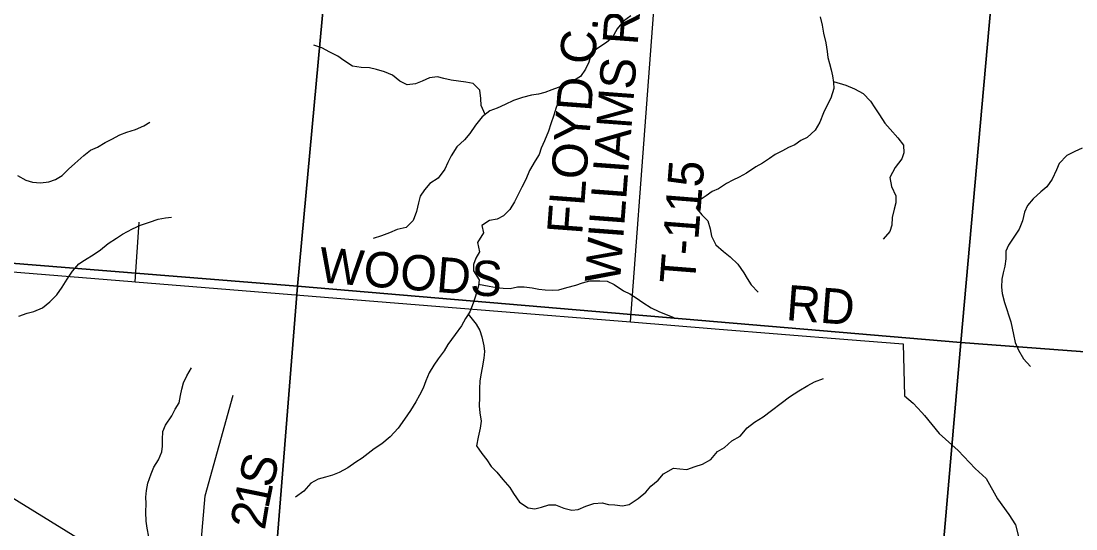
# Model space of a CAD drawing. Extents: x 1715311 to 2083412, y 146837 to 553079.
# Drawn here: x 1957824 to 1966796, y 323512 to 327826 of the extents above; entities that cross this region are included whole.
import ezdxf

# ---------------------------------------------------------------- set-up
doc = ezdxf.new("R2010")
doc.units = 0
for name, color, linetype in [('GM_X_Minor_River', 7, 'Continuous'), ('GM_X_Section', 7, 'Continuous'), ('GM_X_State_Route', 7, 'Continuous'), ('GM_X_Township_Road', 7, 'Continuous'), ('GM_X_Township_Road_Text', 7, 'Continuous')]:
    doc.layers.add(name, color=color, linetype=linetype)

msp = doc.modelspace()

# ---------------------------------------------------------------- linework, layer by layer
at = {"layer": 'GM_X_Minor_River'}
for points in [[(1963011.1, 327870.8), (1962949, 327825.1), (1962894.9, 327759.3), (1962852.6, 327683.4), (1962802.6, 327645.6), (1962728.5, 327595.9), (1962676.5, 327558.1), (1962652.2, 327478.2), (1962624, 327418.2), (1962581.8, 327356.4), (1962515.8, 327316.7), (1962461.8, 327286.9), (1962391.8, 327263.2), (1962337.8, 327243.4), (1962277.9, 327219.7), (1962223.9, 327205.9), (1962166, 327196.2), (1962090.1, 327178.5), (1962012.2, 327152.8), (1961942.2, 327119.1), (1961874.2, 327085.4), (1961810.2, 327063.7), (1961746.2, 327013.9), (1961690, 326942.1), (1961639.8, 326870.3), (1961595.6, 326816.5), (1961531.5, 326758.7), (1961481.3, 326680.9), (1961453.1, 326625), (1961426.9, 326569), (1961370.7, 326493.2), (1961300.7, 326445.5), (1961254.6, 326393.7), (1961218.4, 326339.8), (1961204.2, 326281.8), (1961185.9, 326207.9), (1961159.6, 326131.9), (1961099.5, 326074.1), (1961023.6, 326056.5), (1960957.6, 326028.8), (1960889.7, 326003), (1960819.7, 325979.3)], [(1964621.5, 327861.5), (1964637.1, 327791.4), (1964648.8, 327723.3), (1964668.4, 327643.1), (1964680.1, 327569), (1964685.8, 327517), (1964699.6, 327466.9), (1964715.3, 327412.8), (1964727.1, 327360.7), (1964734.8, 327304.6), (1964736.6, 327252.5), (1964712.3, 327170.6), (1964684.1, 327116.7), (1964649.9, 327046.8), (1964617.6, 326966.9), (1964579.4, 326899), (1964509.3, 326837.3), (1964457.3, 326811.5), (1964405.2, 326775.7), (1964351.3, 326751.9), (1964299.3, 326724.1), (1964239.3, 326694.4), (1964189.2, 326658.6), (1964129.2, 326618.8), (1964073.2, 326587), (1963993.1, 326535.4), (1963931.1, 326499.6), (1963879.1, 326473.8), (1963825.1, 326446.1), (1963755.1, 326400.4), (1963703.1, 326378.6), (1963651, 326342.8), (1963601, 326309), (1963564.8, 326239.1), (1963614.4, 326180.8), (1963664.1, 326128.6), (1963685.7, 326060.4), (1963695.5, 326000.3), (1963733, 325924.1), (1963798.7, 325869.8), (1963856.3, 325823.5), (1963921.9, 325761.1), (1963971.5, 325688.8), (1963999.2, 325638.7), (1964034.9, 325586.5), (1964092.5, 325522.2)], [(1961771.1, 327033.3), (1961736.6, 327110), (1961734.9, 327170.1), (1961725.2, 327240.2), (1961669.6, 327296.5), (1961607.7, 327306.8), (1961482.1, 327325.4), (1961418.3, 327339.7), (1961366.5, 327353.9), (1961296.6, 327344.2), (1961236.6, 327316.5), (1961178.6, 327292.7), (1961108.7, 327285), (1961045, 327317.3), (1960983.4, 327367.6), (1960915.6, 327396), (1960847.9, 327416.3), (1960786.1, 327428.6), (1960716.3, 327430.9), (1960642.5, 327443.2), (1960568.8, 327491.6), (1960517.1, 327527.9), (1960451.4, 327562.2), (1960381.7, 327600.5), (1960314, 327622.9)], [(1964733.5, 327314.1), (1964840.5, 327282.1), (1964914.2, 327251.7), (1964987.9, 327211.4), (1965049.4, 327147), (1965085.1, 327090.8), (1965124.8, 327030.6), (1965170.4, 326960.3), (1965216, 326908.1), (1965281.6, 326833.8), (1965329.2, 326771.5), (1965332.9, 326707.4), (1965314.7, 326655.5), (1965258.5, 326581.7), (1965214.3, 326497.8), (1965227.9, 326421.7), (1965265.5, 326341.5), (1965263.2, 326281.4), (1965249, 326227.5), (1965234.7, 326157.5), (1965230.5, 326091.4), (1965212.3, 326037.5), (1965158.1, 325973.7)], [(1962422.2, 327273.5), (1962411.5, 327199), (1962393.3, 327137.1), (1962373.1, 327085.1), (1962354.9, 327027.2), (1962330.6, 326953.2), (1962310.4, 326891.3), (1962276.1, 326809.4), (1962247.9, 326747.5), (1962229.7, 326693.5), (1962195.5, 326639.6), (1962149.3, 326555.8), (1962117, 326479.8), (1962082.8, 326416), (1962052.6, 326352), (1962020.4, 326292.1), (1961982.2, 326226.3), (1961928.1, 326172.5), (1961872.1, 326142.7), (1961808.2, 326133), (1961744.2, 326089.2), (1961757.9, 326027.1), (1961705.6, 325945.3), (1961723.2, 325865.2), (1961691.1, 325813.3), (1961672.9, 325757.3), (1961672.6, 325705.3), (1961720.2, 325627), (1961714, 325577), (1961687.7, 325489), (1961669.5, 325429.1), (1961641.2, 325357.2), (1961605, 325299.3), (1961570.8, 325237.4), (1961516.6, 325163.6), (1961454.4, 325079.8), (1961422.2, 325023.9), (1961372.1, 324958.1), (1961333.9, 324904.2), (1961293.7, 324838.3), (1961267.5, 324770.4), (1961243.3, 324706.5), (1961213.1, 324648.6), (1961180.9, 324590.7), (1961136.7, 324516.8), (1961086.5, 324443), (1961032.3, 324369.2), (1960962.1, 324293.4), (1960892, 324233.7), (1960827.9, 324192), (1960775.9, 324152.2), (1960725.8, 324112.4), (1960671.8, 324078.6), (1960601.7, 324030.9), (1960529.7, 323991.2), (1960473.8, 323969.4), (1960413.8, 323951.7), (1960351.9, 323935.9), (1960287.9, 323900.2), (1960229.7, 323832.4), (1960157.7, 323782.7)], [(1957792.8, 326515.4), (1957864.4, 326475.1), (1957920.2, 326456.8), (1957990.1, 326452.5), (1958059.9, 326460.2), (1958115.9, 326479.9), (1958173.9, 326515.7), (1958226, 326569.5), (1958280.1, 326617.3), (1958358.2, 326685), (1958414.3, 326728.8), (1958472.3, 326756.5), (1958538.3, 326796.3), (1958596.3, 326824), (1958664.3, 326859.8), (1958722.3, 326883.5), (1958796.2, 326905.2), (1958868.2, 326936.9), (1958920.2, 326966.7)], [(1966849.7, 326746.6), (1966787.7, 326718.8), (1966717.7, 326685.1), (1966653.6, 326615.4), (1966631.4, 326561.4), (1966595.1, 326483.5), (1966549, 326417.7), (1966498.9, 326375.9), (1966432.8, 326316.1), (1966384.6, 326258.3), (1966358.5, 326202.4), (1966342.2, 326130.4), (1966313.9, 326058.5), (1966263.7, 325982.7), (1966221.5, 325922.8), (1966199.4, 325870.9), (1966199.1, 325806.8), (1966192.8, 325744.8), (1966176.6, 325686.8), (1966166.4, 325634.8), (1966162.1, 325566.8), (1966169.9, 325512.7), (1966187.5, 325434.6), (1966205.2, 325384.5), (1966224.9, 325322.3), (1966242.7, 325272.2), (1966254.4, 325216.1), (1966264.2, 325164), (1966279.8, 325095.9), (1966307.5, 325029.7), (1966351.1, 324955.5), (1966410.6, 324891.2)], [(1957803.5, 325318.5), (1957875.5, 325344.2), (1957933.4, 325357.9), (1958005.4, 325391.6), (1958069.5, 325441.4), (1958127.6, 325501.1), (1958173.8, 325567), (1958216, 325632.8), (1958260.2, 325702.7), (1958314.3, 325764.5), (1958364.4, 325794.3), (1958444.4, 325846), (1958498.5, 325883.8), (1958564.5, 325935.5), (1958634.6, 325983.2), (1958686.6, 326015), (1958770.6, 326060.7), (1958840.6, 326092.4), (1958916.5, 326118), (1958988.5, 326143.8), (1959052.4, 326155.5), (1959104.3, 326161.2)], [(1961715.6, 325590), (1961805.8, 325574.6), (1961867.6, 325562.3), (1961925.4, 325556), (1961983.3, 325555.8), (1962047.2, 325567.5), (1962103.1, 325569.2), (1962170.9, 325558.9), (1962226.7, 325548.6), (1962280.6, 325544.4), (1962340.5, 325540.1), (1962398.3, 325543.9), (1962466.3, 325563.6), (1962542.2, 325583.2), (1962600.1, 325603), (1962662.1, 325620.7), (1962745.9, 325620.3), (1962809.7, 325616), (1962867.5, 325589.8), (1962949.1, 325533.4), (1963002.9, 325509.1), (1963054.6, 325474.8), (1963112.3, 325434.5), (1963181.9, 325390.2), (1963249.7, 325357.9), (1963311.4, 325333.6), (1963377.2, 325307.2)], [(1961628, 325336), (1961694.6, 325250.8), (1961726.3, 325198.6), (1961742.1, 325144.5), (1961759.7, 325068.4), (1961765.5, 325018.3), (1961761.2, 324962.3), (1961746.9, 324880.3), (1961734.7, 324820.3), (1961724.5, 324766.3), (1961722.2, 324704.3), (1961721.9, 324628.2), (1961719.6, 324556.2), (1961727.3, 324498.1), (1961737, 324426), (1961728.7, 324368), (1961710.4, 324292), (1961698.1, 324218), (1961741.8, 324151.8), (1961785.4, 324097.6), (1961823.1, 324043.3), (1961870.8, 323993.1), (1961922.4, 323932.8), (1961980, 323864.5), (1962011.7, 323812.3), (1962063.2, 323738), (1962136.9, 323691.7), (1962194.7, 323681.4), (1962250.7, 323697.1), (1962312.6, 323716.9), (1962368.5, 323716.6), (1962440.2, 323688.3), (1962508, 323670), (1962561.9, 323675.7), (1962627.9, 323705.4), (1962695.8, 323729.1), (1962765.7, 323732.8), (1962819.5, 323720.6), (1962875.4, 323716.3), (1962939.2, 323708), (1962997.1, 323719.8), (1963073.2, 323769.5), (1963137.2, 323823.2), (1963181.4, 323875.1), (1963241.5, 323924.8), (1963289.6, 323980.6), (1963373.6, 324028.3), (1963427.5, 324022), (1963485.3, 324015.8), (1963557.3, 324043.5), (1963619.2, 324061.2), (1963691.2, 324102.9), (1963747.4, 324170.7), (1963807.4, 324204.5), (1963869.5, 324260.2), (1963939.5, 324299.9), (1963999.7, 324371.7), (1964061.8, 324419.5), (1964135.8, 324465.2), (1964205.9, 324516.9), (1964288, 324580.6), (1964360.1, 324634.3), (1964440.1, 324686), (1964516.1, 324731.6), (1964572.1, 324761.4), (1964650.1, 324791.1)], [(1958909, 323444.1), (1958897.3, 323518.2), (1958887.6, 323576.3), (1958883.9, 323654.4), (1958888.2, 323726.4), (1958884.5, 323780.5), (1958890.7, 323838.5), (1958901, 323900.5), (1958929.2, 323978.4), (1958953.4, 324036.3), (1958991.6, 324098.2), (1959019.8, 324166.1), (1959026, 324216.1), (1959026.3, 324272.2), (1959030.6, 324338.2), (1959050.8, 324394.2), (1959107, 324472), (1959135.2, 324527.9), (1959167.3, 324581.8), (1959179.6, 324645.8), (1959191.8, 324699.8), (1959204, 324751.7), (1959234.2, 324813.6), (1959274.4, 324879.5)]]:
    msp.add_lwpolyline(points, dxfattribs=at)
at = {"layer": 'GM_X_Section'}
for points in [[(1960667.9, 330918.2), (1960176.2, 325575.7), (1954563.6, 326023.5), (1954897.2, 331252.1)], [(1960667.9, 330918.2), (1966300.5, 330486.3), (1965818.8, 325095.8), (1960176.2, 325575.7)], [(1966300.5, 330486.3), (1971868, 329980.4), (1971431.7, 324673.2), (1965818.8, 325095.8)], [(1954563.6, 326023.5), (1960176.2, 325575.7), (1959744.5, 320189.1), (1954105.8, 320629)], [(1960176.2, 325575.7), (1965818.8, 325095.8), (1965361.2, 319827.2), (1959744.5, 320189.1)], [(1965818.8, 325095.8), (1971431.7, 324673.2), (1971001.4, 319276), (1965361.2, 319827.2)]]:
    msp.add_lwpolyline(points, close=True, dxfattribs=at)
at = {"layer": 'GM_X_State_Route'}
msp.add_lwpolyline([(1952758, 326079.9), (1952855.9, 326058), (1953116, 325883.6), (1954496.8, 325911.9), (1955769.4, 324997.5), (1958874.9, 323084.4), (1959307.8, 322840.8), (1960540.6, 322714.5), (1961879.5, 321752.1), (1962403.9, 321517.6), (1963838.9, 321035.1), (1963965.3, 320991.3), (1964281.5, 320971.3), (1965388.2, 320901.5), (1965711.6, 320881), (1966211.2, 320756.8), (1966668.3, 320492.4), (1967805.6, 319697)], dxfattribs=at)
at = {"layer": 'GM_X_Township_Road'}
for points in [[(1963008.2, 325270.6), (1963286.6, 328978)], [(1958792.7, 325611), (1958826.8, 326119.2)], [(1955929.3, 325842), (1958765, 325613.2), (1958792.7, 325611), (1960510.4, 325472.3), (1960578.2, 325466.8)], [(1960578.2, 325466.8), (1961807.4, 325367.6), (1963008.2, 325270.6), (1963726.8, 325212.6), (1963727.4, 325212.6)], [(1963727.4, 325212.6), (1964855.5, 325121.4), (1965326.7, 325083.4), (1965338.7, 324642.4), (1965412.2, 324580.6), (1965484.5, 324501)], [(1959307.8, 322840.8), (1959390.4, 323793), (1959626.8, 324648.7)], [(1965484.5, 324501), (1965484.7, 324500.9), (1965507.8, 324475.4), (1965632.2, 324322.3), (1965794.8, 324178.8), (1965938.3, 324025.8), (1966033.9, 323939.7), (1966129.6, 323767.5), (1966225.2, 323633.5), (1966282.6, 323547.5), (1966330.5, 323356.1)]]:
    msp.add_lwpolyline(points, dxfattribs=at)

# ---------------------------------------------------------------- texts
at = {"layer": 'GM_X_Township_Road_Text'}
for s, rotation, p in [('WILLIAMS RD', 85.7444, (1962917.6, 325594.4)), ('FLOYD C.', 85.71848, (1962596, 326007.5)), ('T-115', 85.49271, (1963554.5, 325585.8)), ('WOODS', 355.31424, (1960349.6, 325607.8)), ('RD', 355.56412, (1964324.9, 325286.7)), ('S', 76.52447, (1959961.7, 323850.8)), ('1', 78.59192, (1959926.1, 323673.9)), ('2', 80.61657, (1959896.7, 323495.7))]:
    msp.add_text(s, height=300, rotation=rotation, dxfattribs=at).set_placement(p)

doc.saveas('drawing.dxf')
